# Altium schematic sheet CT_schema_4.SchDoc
size 205 x 258 mm
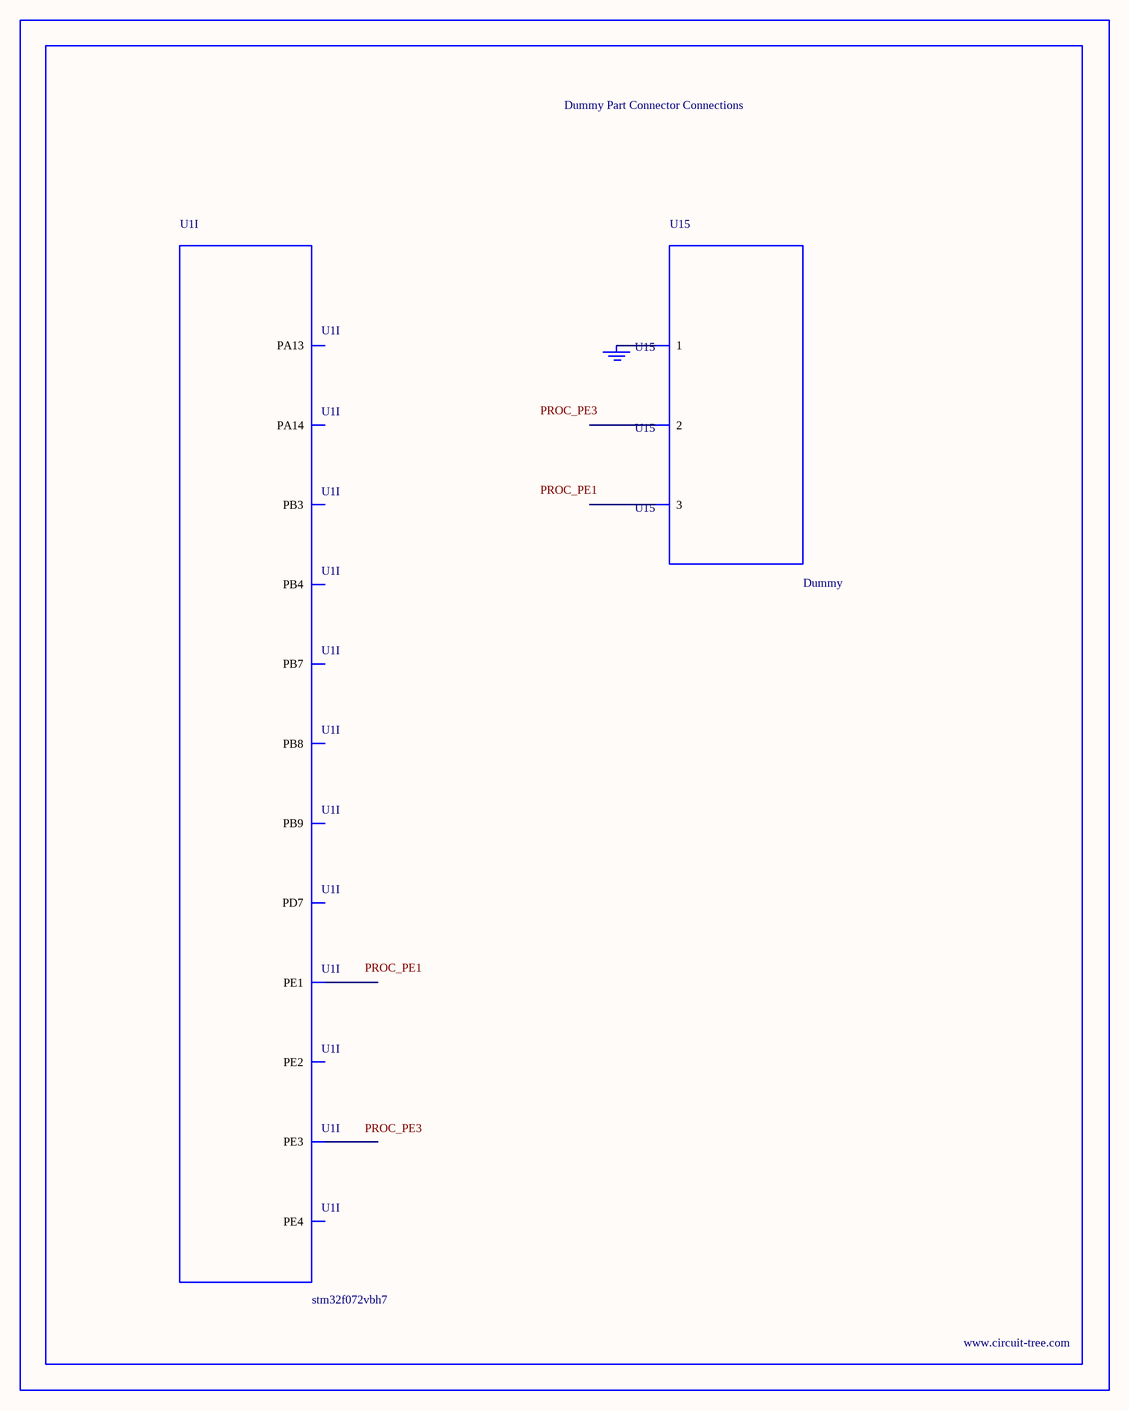
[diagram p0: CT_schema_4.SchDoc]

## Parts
BORDER3  (no value)
GND_INSTANCE_3_0  (no value)
U1  stm32f072vbh7  [UFBGA100]  (part I of 9)
U15  Dummy  [DUMMY_PACKAGE_117]

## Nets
NetGND_INSTANCE_3_0_0: GND_INSTANCE_3_0.0(GND) U15.1

Not connected (* = marked no-connect by the designer): U1 A1(PE3) A2(PE1) A3(PB8) A5(PD7) A7(PB4) A8(PB3) A10(PA14) A11(PA13) B1(PE4) B2(PE2) B3(PB9) B4(PB7); U15 2 3

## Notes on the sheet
- Labels drawn without touching a wire or pin: PROC_PE1, PROC_PE3

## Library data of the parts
BORDER3 = BORDER_PAGE3
GND_INSTANCE_3_0 = GND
